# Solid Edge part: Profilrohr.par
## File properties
Username: bmolnar
Dokumentum tartalom típus: 0
Author: bmolnar
Last saved by: bmolnar
Revision: 79
Sűrűség: 0,000 kg/m^3
Pontosság: 0,990
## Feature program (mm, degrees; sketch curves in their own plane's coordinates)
base feature "unnamed BaseFeature 1"
thread "unnamed Thread 1"
thread "Menet_2"  ThreadDepth = 6.5 mm
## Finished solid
Body 1: solid body, 139 faces, 302 edges, 192 vertices, 3 separate solids.
  Faces by surface: plane 61, cylinder 60, cone 16, torus 2
  Edges by curve: line 150, circle 148, curve on surface 3, intersection 1
Bounding box of the edges (mm; curved faces can reach further): 40.000 x 44.500 x 53.500, from (-20, -20, 0) to (20, 24.5, 53.5).
Cylindrical faces by radius (mm): R0.3 x24, R0.8 x2, R2.5 x2, R2.85 x6, R4.283 x4, R4.35 x2, R4.4 x7, R4.5 x2, R12.5 x1, R13.45 x2, R13.5 x2, R14.2 x2, R27 x4
Conical faces (half-angle, radius in mm at the cone's reference point): 30 deg R4.0613 x2, 30 deg R12.85 x2, 30 deg R13.6232 x2, 45 deg R2.75 x4, 45 deg R4.1 x2, 45 deg R4.533 x2, 45 deg R13.65 x2
Toroidal faces (ring radius, tube radius in mm): R14 r0.2 x2
Planar faces by outward normal: +x 6, +y 9, +z 11, -x 6, -y 7, -z 10, oblique 12
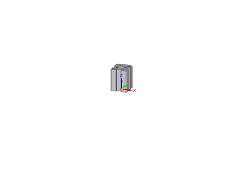
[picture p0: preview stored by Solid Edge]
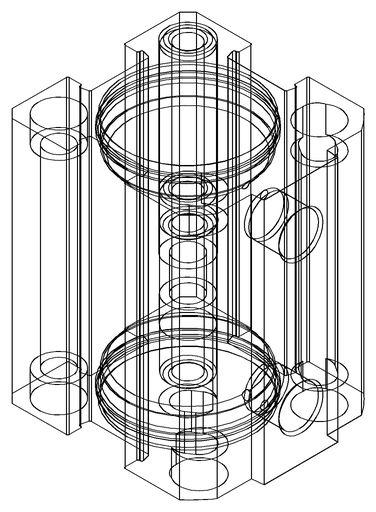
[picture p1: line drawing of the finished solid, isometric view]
